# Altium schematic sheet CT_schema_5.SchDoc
size 218 x 258 mm
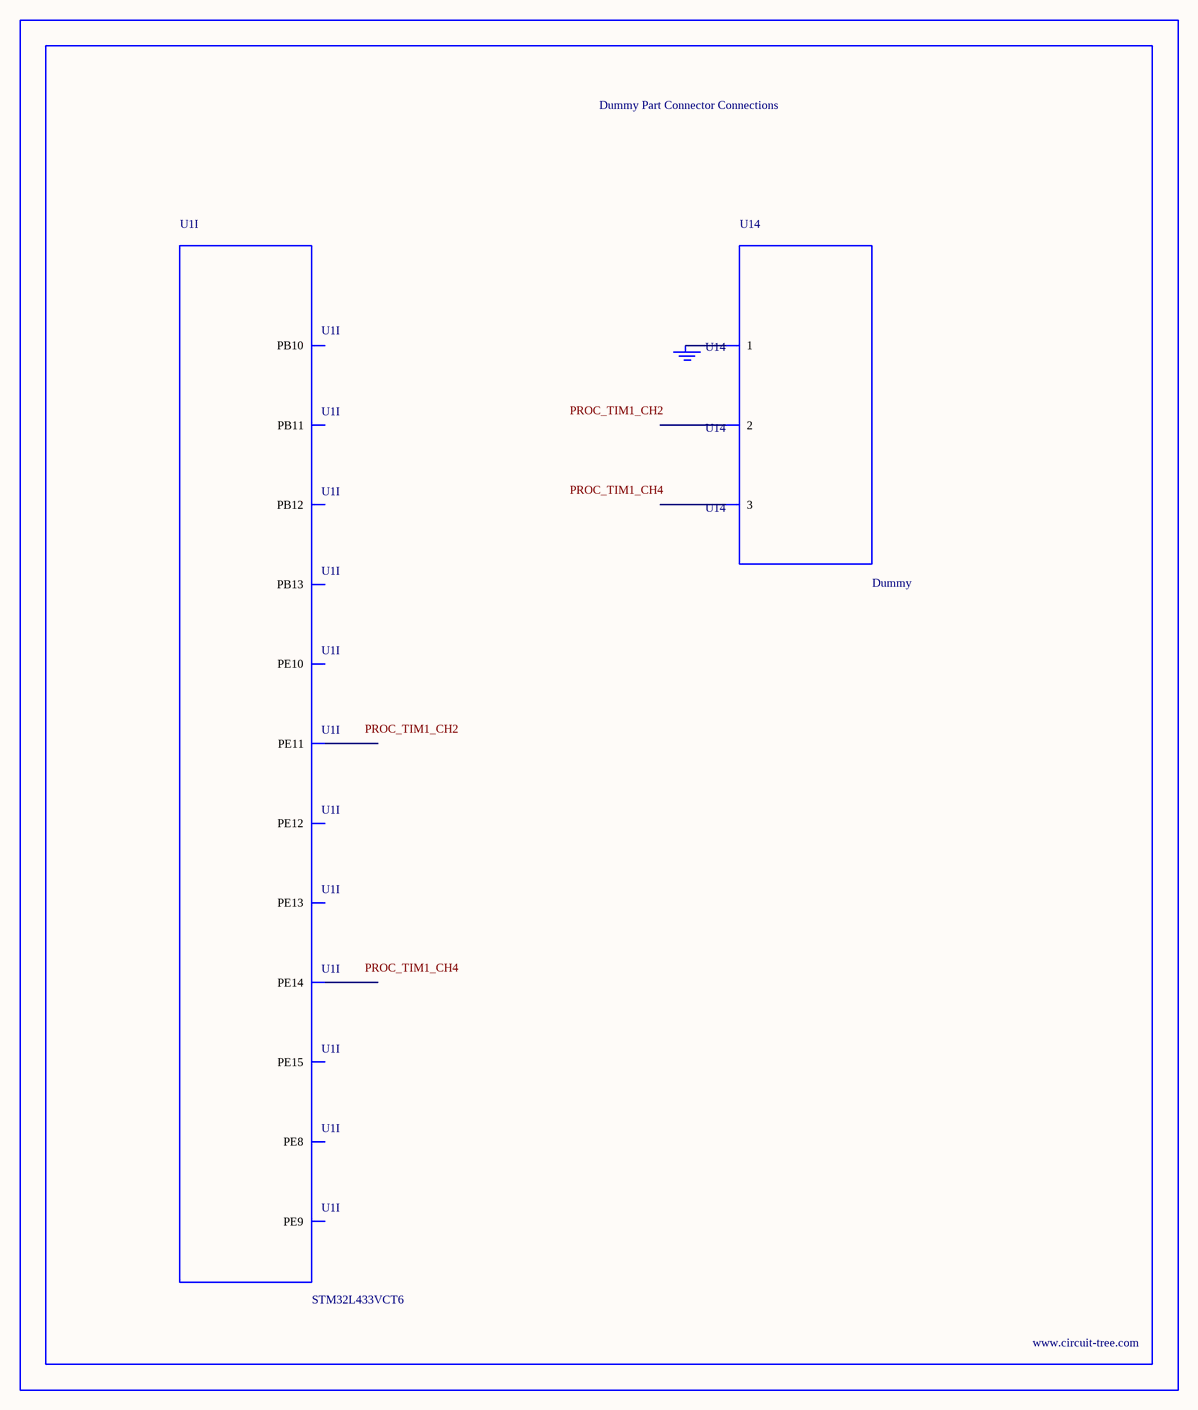
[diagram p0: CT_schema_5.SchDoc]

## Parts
BORDER4  (no value)
GND_INSTANCE_4_0  (no value)
U1  STM32L433VCT6  [LQFP100]  (part I of 9)
U14  Dummy  [DUMMY_PACKAGE_138]

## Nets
NetGND_INSTANCE_4_0_0: GND_INSTANCE_4_0.0(GND) U14.1

Not connected (* = marked no-connect by the designer): U1 39(PE8) 40(PE9) 41(PE10) 42(PE11) 43(PE12) 44(PE13) 45(PE14) 46(PE15) 47(PB10) 48(PB11) 51(PB12) 52(PB13); U14 2 3

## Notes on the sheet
- Labels drawn without touching a wire or pin: PROC_TIM1_CH2, PROC_TIM1_CH4

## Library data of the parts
BORDER4 = BORDER_PAGE4
GND_INSTANCE_4_0 = GND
